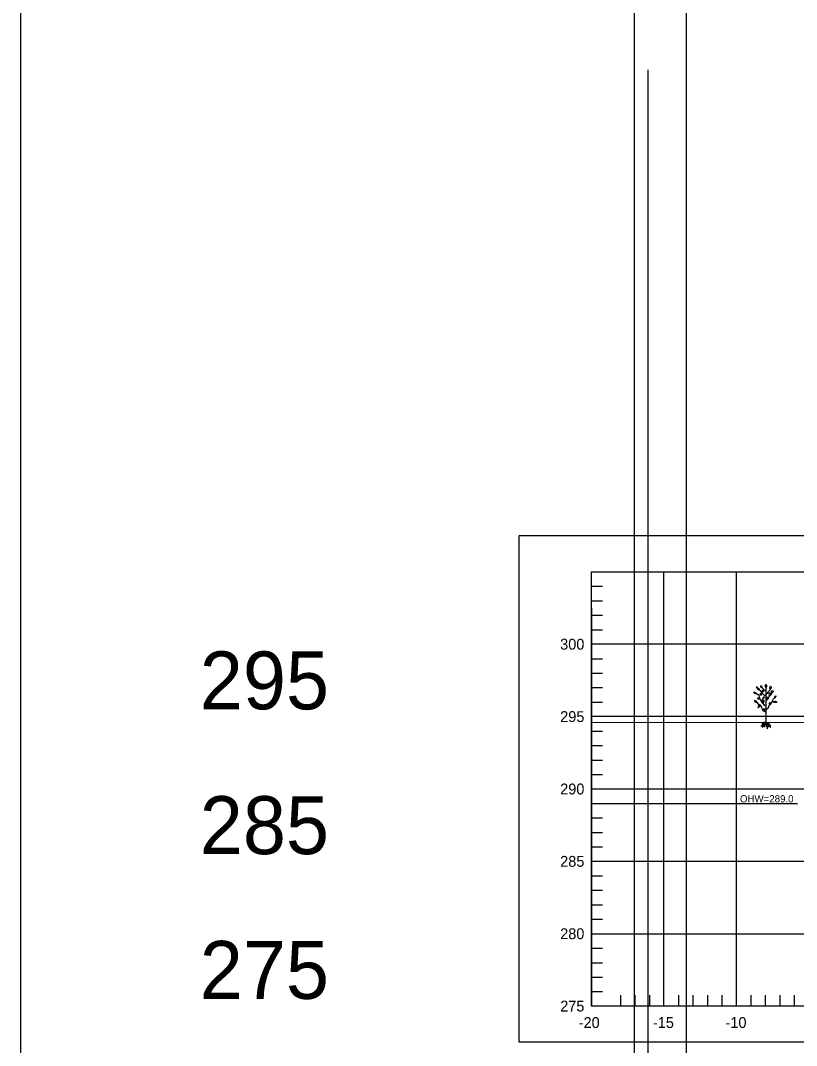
# Model space of a CAD drawing. Extents: x 1578769 to 1579225, y 724002 to 724828.
# Drawn here: x 1578781.8 to 1578835.4, y 724434.8 to 724505.6 of the extents above; entities that cross this region are included whole.
import ezdxf

# ---------------------------------------------------------------- set-up
doc = ezdxf.new("R2010")
doc.units = 0
for name, color, linetype in [('1', 7, 'Continuous'), ('Default', 7, 'Continuous'), ('Old_Level_1', 7, 'Continuous'), ('Old_Level_41', 7, 'Continuous'), ('Old_Level_42', 7, 'Continuous'), ('R_Exist Surface', 7, 'Continuous')]:
    doc.layers.add(name, color=color, linetype=linetype)

msp = doc.modelspace()

# ---------------------------------------------------------------- linework, layer by layer
at = {"layer": '1'}
for p, q in [((1578833.285, 724457.082), (1578833.285, 724459.482)), ((1578833.29, 724457.077), (1578833.292, 724457.081)), ((1578821.23, 724451.474), (1578835.459, 724451.474))]:
    msp.add_line(p, q, dxfattribs=at)
for points in [[(1578833.285, 724459.482), (1578833.241, 724459.545), (1578833.228, 724459.571), (1578833.241, 724459.621), (1578833.254, 724459.646), (1578833.279, 724459.703), (1578833.298, 724459.697), (1578833.317, 724459.646), (1578833.323, 724459.608), (1578833.329, 724459.571)], [(1578832.831, 724459.305), (1578832.755, 724459.312), (1578832.711, 724459.356), (1578832.686, 724459.4), (1578832.641, 724459.514), (1578832.629, 724459.552), (1578832.705, 724459.482), (1578832.749, 724459.438), (1578832.799, 724459.387)], [(1578833.033, 724459.065), (1578832.992, 724459.058), (1578832.935, 724459.049), (1578832.906, 724459.049), (1578832.896, 724459.02), (1578832.849, 724459.02), (1578832.877, 724458.982), (1578832.915, 724458.982), (1578832.963, 724458.982), (1578833.001, 724459.02)], [(1578833.033, 724459.444), (1578832.951, 724459.482), (1578832.925, 724459.52), (1578832.913, 724459.583), (1578832.913, 724459.608), (1578832.951, 724459.589), (1578832.995, 724459.539)], [(1578833.146, 724459.293), (1578833.078, 724459.278), (1578833.049, 724459.278), (1578833.02, 724459.268), (1578833.02, 724459.23), (1578832.992, 724459.202), (1578833.011, 724459.192), (1578833.068, 724459.192), (1578833.106, 724459.211), (1578833.125, 724459.259)], [(1578832.696, 724458.418), (1578832.61, 724458.437), (1578832.534, 724458.475), (1578832.524, 724458.533), (1578832.486, 724458.609), (1578832.543, 724458.581), (1578832.581, 724458.552), (1578832.639, 724458.495), (1578832.667, 724458.456)], [(1578833.071, 724458.408), (1578833.078, 724458.485), (1578833.068, 724458.504), (1578833.087, 724458.561), (1578833.116, 724458.6), (1578833.125, 724458.6), (1578833.135, 724458.542), (1578833.135, 724458.495)], [(1578833.071, 724458.674), (1578833.09, 724458.768), (1578833.102, 724458.806), (1578833.108, 724458.825), (1578833.134, 724458.85), (1578833.153, 724458.85), (1578833.153, 724458.781), (1578833.14, 724458.756)], [(1578832.896, 724458.265), (1578832.839, 724458.227), (1578832.763, 724458.208), (1578832.744, 724458.151), (1578832.744, 724458.112), (1578832.715, 724458.093), (1578832.753, 724458.103), (1578832.83, 724458.17), (1578832.839, 724458.17), (1578832.896, 724458.237)]]:
    msp.add_lwpolyline(points, close=True, dxfattribs=at)
for points in [[(1578832.667, 724459.027), (1578832.623, 724459.04), (1578832.547, 724459.046), (1578832.515, 724459.065), (1578832.477, 724459.122), (1578832.452, 724459.185), (1578832.452, 724459.192), (1578832.49, 724459.16), (1578832.541, 724459.135), (1578832.61, 724459.091), (1578832.667, 724459.027)], [(1578833.285, 724458.181), (1578833.172, 724458.257), (1578833.071, 724458.408), (1578832.97, 724458.522), (1578832.856, 724458.737), (1578832.806, 724458.926), (1578832.667, 724459.027)], [(1578833.273, 724458.888), (1578833.222, 724458.914), (1578833.121, 724458.989), (1578833.033, 724459.065), (1578832.944, 724459.154), (1578832.932, 724459.229), (1578832.932, 724459.242), (1578832.831, 724459.305)], [(1578833.285, 724459.242), (1578833.197, 724459.267), (1578833.146, 724459.293), (1578833.121, 724459.343), (1578833.045, 724459.432), (1578833.033, 724459.444)], [(1578833.285, 724459.065), (1578833.361, 724459.065), (1578833.424, 724459.154), (1578833.449, 724459.217), (1578833.563, 724459.33), (1578833.575, 724459.368)], [(1578833.285, 724458.598), (1578833.298, 724458.598), (1578833.374, 724458.674), (1578833.437, 724458.699), (1578833.525, 724458.876), (1578833.601, 724458.952), (1578833.651, 724459.027), (1578833.664, 724459.065)], [(1578833.519, 724458.977), (1578833.493, 724459.04), (1578833.506, 724459.116), (1578833.525, 724459.147), (1578833.557, 724459.097), (1578833.557, 724459.04), (1578833.519, 724458.977)], [(1578833.572, 724459.368), (1578833.541, 724459.425), (1578833.541, 724459.482), (1578833.56, 724459.526), (1578833.585, 724459.577), (1578833.61, 724459.583), (1578833.635, 724459.501), (1578833.635, 724459.463), (1578833.629, 724459.432), (1578833.579, 724459.368)], [(1578833.664, 724459.065), (1578833.651, 724459.185), (1578833.664, 724459.229), (1578833.714, 724459.28), (1578833.746, 724459.248), (1578833.765, 724459.179), (1578833.721, 724459.128), (1578833.664, 724459.078)], [(1578832.856, 724458.737), (1578832.782, 724458.743), (1578832.725, 724458.743), (1578832.686, 724458.743), (1578832.705, 724458.724), (1578832.744, 724458.695), (1578832.782, 724458.686), (1578832.858, 724458.733)], [(1578833.288, 724457.778), (1578833.25, 724457.788), (1578833.173, 724457.835), (1578833.078, 724457.883), (1578833.02, 724458.007), (1578832.982, 724458.112), (1578832.896, 724458.265), (1578832.791, 724458.313), (1578832.696, 724458.418), (1578832.696, 724458.418)], [(1578832.97, 724458.522), (1578832.989, 724458.585), (1578833.039, 724458.623), (1578833.071, 724458.674)], [(1578833.285, 724457.973), (1578833.449, 724458.093), (1578833.5, 724458.257), (1578833.613, 724458.345), (1578833.702, 724458.522), (1578833.79, 724458.699), (1578833.853, 724458.749)], [(1578833.374, 724458.674), (1578833.348, 724458.737), (1578833.361, 724458.813), (1578833.38, 724458.844), (1578833.411, 724458.794), (1578833.411, 724458.737), (1578833.374, 724458.674)], [(1578833.525, 724458.876), (1578833.519, 724458.914), (1578833.5, 724458.939), (1578833.519, 724458.977)], [(1578833.555, 724458.308), (1578833.529, 724458.371), (1578833.542, 724458.447), (1578833.561, 724458.479), (1578833.592, 724458.428), (1578833.592, 724458.371), (1578833.555, 724458.308)], [(1578833.702, 724458.522), (1578833.765, 724458.522), (1578833.79, 724458.522), (1578833.822, 724458.509)], [(1578833.822, 724458.509), (1578833.91, 724458.541), (1578833.973, 724458.516), (1578834.017, 724458.497), (1578834.017, 724458.465), (1578833.998, 724458.446), (1578833.967, 724458.44), (1578833.923, 724458.446), (1578833.872, 724458.446), (1578833.822, 724458.509)], [(1578833.853, 724458.749), (1578833.885, 724458.832), (1578833.916, 724458.895), (1578833.96, 724458.907), (1578833.967, 724458.876), (1578833.948, 724458.819), (1578833.91, 724458.781), (1578833.853, 724458.749)], [(1578833.134, 724457.869), (1578833.109, 724457.932), (1578833.122, 724458.008), (1578833.141, 724458.039), (1578833.172, 724457.989), (1578833.172, 724457.932), (1578833.134, 724457.869)], [(1578833.285, 724457.082), (1578833.234, 724457.076), (1578833.218, 724457.08), (1578833.16, 724457.072), (1578833.125, 724457.065), (1578833.098, 724457.049), (1578833.067, 724457.018), (1578833.044, 724456.983), (1578833.036, 724456.948), (1578833.036, 724456.917), (1578833.02, 724456.882), (1578833.009, 724456.867), (1578832.97, 724456.839), (1578832.935, 724456.793)], [(1578833.067, 724457.018), (1578833.024, 724456.999), (1578833.009, 724456.975), (1578832.997, 724456.968)], [(1578833.285, 724457.082), (1578833.218, 724457.034), (1578833.179, 724457.014), (1578833.141, 724456.983), (1578833.121, 724456.944), (1578833.113, 724456.913), (1578833.075, 724456.828), (1578833.04, 724456.785), (1578833.028, 724456.735), (1578833.013, 724456.692)], [(1578833.141, 724456.983), (1578833.098, 724456.975), (1578833.094, 724456.96)], [(1578833.199, 724456.882), (1578833.152, 724456.843), (1578833.148, 724456.824), (1578833.141, 724456.82), (1578833.121, 724456.762)], [(1578833.285, 724457.082), (1578833.245, 724456.987), (1578833.21, 724456.933), (1578833.199, 724456.882), (1578833.183, 724456.843), (1578833.172, 724456.785), (1578833.172, 724456.746)], [(1578833.245, 724456.987), (1578833.245, 724456.933), (1578833.249, 724456.909), (1578833.261, 724456.878)], [(1578833.285, 724457.082), (1578833.369, 724457.066), (1578833.412, 724457.053), (1578833.439, 724457.034), (1578833.467, 724456.995), (1578833.486, 724456.948), (1578833.552, 724456.902), (1578833.575, 724456.874), (1578833.575, 724456.816), (1578833.579, 724456.758), (1578833.618, 724456.719)], [(1578833.285, 724457.082), (1578833.354, 724457.045), (1578833.377, 724456.991), (1578833.389, 724456.937), (1578833.424, 724456.89), (1578833.447, 724456.805), (1578833.47, 724456.754)], [(1578833.285, 724457.082), (1578833.292, 724457.018), (1578833.304, 724456.991), (1578833.315, 724456.952), (1578833.323, 724456.937), (1578833.323, 724456.905), (1578833.311, 724456.867), (1578833.323, 724456.82), (1578833.339, 724456.785), (1578833.358, 724456.746), (1578833.358, 724456.711), (1578833.37, 724456.669), (1578833.393, 724456.634)], [(1578833.377, 724456.991), (1578833.366, 724456.96), (1578833.354, 724456.944), (1578833.373, 724456.898)], [(1578833.424, 724456.89), (1578833.459, 724456.871), (1578833.478, 724456.859), (1578833.49, 724456.847)], [(1578833.552, 724456.902), (1578833.54, 724456.863), (1578833.536, 724456.843)], [(1578833.075, 724456.828), (1578833.067, 724456.773), (1578833.071, 724456.758)], [(1578833.323, 724456.82), (1578833.358, 724456.805), (1578833.381, 724456.785), (1578833.385, 724456.77)], [(1578833.358, 724456.711), (1578833.331, 724456.676), (1578833.335, 724456.653)]]:
    msp.add_lwpolyline(points, dxfattribs=at)
at = {"layer": 'Default'}
for p, q in [((1578781.789, 724578.446), (1578781.789, 724328.446)), ((1578824.194, 724303.15), (1578824.194, 724553.15)), ((1578827.766, 724526.976), (1578827.766, 724276.976)), ((1578825.136, 724252.141), (1578825.136, 724502.141))]:
    msp.add_line(p, q, dxfattribs=at)
at = {"layer": 'Old_Level_1'}
for points in [[(1578816.23, 724469.974), (1578923.73, 724469.974), (1578923.73, 724434.974), (1578816.23, 724434.974)], [(1578821.23, 724467.474), (1578921.23, 724467.474), (1578921.23, 724437.474), (1578821.23, 724437.474)]]:
    msp.add_lwpolyline(points, close=True, dxfattribs=at)
at = {"layer": 'Old_Level_41'}
for p, q in [((1578826.23, 724437.474), (1578826.23, 724467.474)), ((1578831.23, 724467.474), (1578831.23, 724437.474)), ((1578821.23, 724464.974), (1578821.23, 724437.474))]:
    msp.add_line(p, q, dxfattribs=at)
for points in [[(1578921.23, 724462.474), (1578821.23, 724462.474)], [(1578921.23, 724457.474), (1578821.23, 724457.474)], [(1578821.23, 724452.474), (1578921.23, 724452.474)], [(1578921.23, 724447.474), (1578821.23, 724447.474)], [(1578821.23, 724442.474), (1578921.23, 724442.474)]]:
    msp.add_lwpolyline(points, dxfattribs=at)
at = {"layer": 'Old_Level_42'}
for p, q in [((1578821.23, 724466.474), (1578821.98, 724466.474)), ((1578821.23, 724465.474), (1578821.98, 724465.474)), ((1578821.23, 724464.474), (1578821.98, 724464.474)), ((1578821.23, 724463.474), (1578821.98, 724463.474)), ((1578821.23, 724461.474), (1578821.98, 724461.474)), ((1578821.23, 724460.474), (1578821.98, 724460.474)), ((1578821.23, 724459.474), (1578821.98, 724459.474)), ((1578821.23, 724458.474), (1578821.98, 724458.474)), ((1578821.23, 724456.474), (1578821.98, 724456.474)), ((1578821.23, 724455.474), (1578821.98, 724455.474)), ((1578821.23, 724454.474), (1578821.98, 724454.474)), ((1578821.23, 724453.474), (1578821.98, 724453.474)), ((1578821.23, 724451.474), (1578821.98, 724451.474)), ((1578821.23, 724450.474), (1578821.98, 724450.474)), ((1578821.23, 724449.474), (1578821.98, 724449.474)), ((1578821.23, 724448.474), (1578821.98, 724448.474)), ((1578821.23, 724446.474), (1578821.98, 724446.474)), ((1578821.23, 724445.474), (1578821.98, 724445.474)), ((1578821.23, 724444.474), (1578821.98, 724444.474)), ((1578821.23, 724443.474), (1578821.98, 724443.474)), ((1578821.23, 724441.474), (1578821.98, 724441.474)), ((1578821.23, 724440.474), (1578821.98, 724440.474)), ((1578821.23, 724439.474), (1578821.98, 724439.474)), ((1578821.23, 724438.474), (1578821.98, 724438.474)), ((1578823.23, 724438.224), (1578823.23, 724437.474)), ((1578824.23, 724438.224), (1578824.23, 724437.474)), ((1578825.23, 724438.224), (1578825.23, 724437.474)), ((1578827.23, 724438.224), (1578827.23, 724437.474)), ((1578828.23, 724438.224), (1578828.23, 724437.474)), ((1578829.23, 724438.224), (1578829.23, 724437.474)), ((1578830.23, 724438.224), (1578830.23, 724437.474)), ((1578832.23, 724438.224), (1578832.23, 724437.474)), ((1578833.23, 724438.224), (1578833.23, 724437.474)), ((1578834.23, 724438.224), (1578834.23, 724437.474)), ((1578835.23, 724438.224), (1578835.23, 724437.474))]:
    msp.add_line(p, q, dxfattribs=at)
at = {"layer": 'R_Exist Surface'}
msp.add_lwpolyline([(1578821.23, 724457.096), (1578841.203, 724457.073)], dxfattribs=at)

# ---------------------------------------------------------------- texts
at = {"layer": '1'}
for s, height, p in [('300', 0.75, (1578819.064, 724462.099)), ('295', 0.75, (1578819.064, 724457.099)), ('290', 0.75, (1578819.064, 724452.099)), ('OHW=289.0', 0.5, (1578831.484, 724451.546)), ('285', 0.75, (1578819.064, 724447.099)), ('280', 0.75, (1578819.064, 724442.099)), ('275', 0.75, (1578819.064, 724437.099)), ('-20', 0.75, (1578820.345, 724435.964)), ('-15', 0.75, (1578825.472, 724435.964)), ('-10', 0.75, (1578830.484, 724435.964))]:
    msp.add_text(s, height=height, dxfattribs=at).set_placement(p)
at = {"layer": 'Default'}
for s, p in [('     295', (1578786.743, 724457.974)), ('     285', (1578786.743, 724447.974)), ('     275', (1578786.743, 724437.974))]:
    msp.add_text(s, height=4, dxfattribs=at).set_placement(p)

doc.saveas('drawing.dxf')
